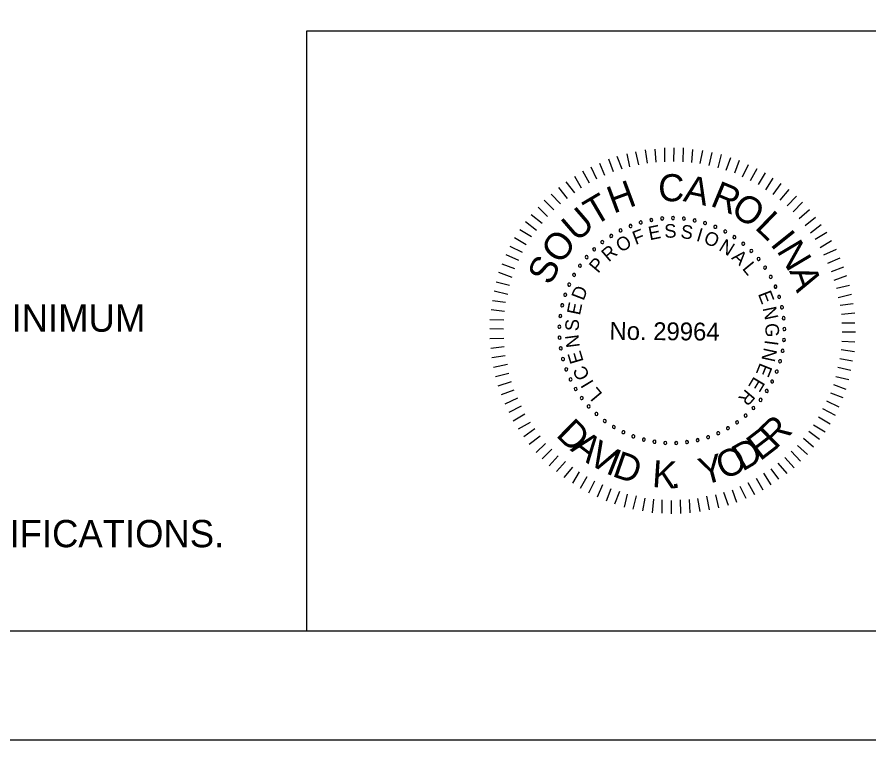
# Model space of a CAD drawing. Extents: x -225.1 to -152.9, y -16.8 to 27.2.
# Drawn here: x -182.47 to -174.66, y -16.78 to -10.15 of the extents above; entities that cross this region are included whole.
import ezdxf

# ---------------------------------------------------------------- set-up
doc = ezdxf.new("R2010")
doc.units = 0
for name, color, linetype in [('BR_BORDER LINES', 7, 'Continuous'), ('BR_TEXT', 7, 'Continuous'), ('Level 31', 7, 'Continuous')]:
    doc.layers.add(name, color=color, linetype=linetype)

msp = doc.modelspace()

# ---------------------------------------------------------------- linework, layer by layer
at = {"layer": 'BR_BORDER LINES'}
for p, q in [((-179.8094, -10.276), (-169.079, -10.276)), ((-179.8094, -15.7761), (-179.8094, -10.276)), ((-221.4105, -15.7762), (-154.0784, -15.7762))]:
    msp.add_line(p, q, dxfattribs=at)
at = {"layer": 'BR_TEXT'}
for p, q in [((-176.8476, -11.5246), (-176.8741, -11.4026)), ((-176.765, -11.5047), (-176.7933, -11.386)), ((-176.686, -11.4899), (-176.7039, -11.3679)), ((-176.607, -11.4819), (-176.6146, -11.3601)), ((-176.528, -11.4774), (-176.5269, -11.3487)), ((-176.4439, -11.4731), (-176.4429, -11.3494)), ((-176.3598, -11.4788), (-176.3553, -11.3502)), ((-176.2792, -11.4847), (-176.2696, -11.3629)), ((-176.202, -11.4939), (-176.1804, -11.3722)), ((-176.1215, -11.51), (-176.093, -11.3918)), ((-176.9991, -11.5697), (-177.0409, -11.4526)), ((-176.9199, -11.5446), (-176.9636, -11.4293)), ((-176.0393, -11.5313), (-176.0073, -11.4097)), ((-175.9657, -11.5525), (-175.9218, -11.4379)), ((-175.8869, -11.5789), (-175.843, -11.4625)), ((-177.1506, -11.6371), (-177.2029, -11.5251)), ((-177.0765, -11.6034), (-177.1237, -11.4914)), ((-175.8151, -11.6138), (-175.7593, -11.5027)), ((-175.7433, -11.6488), (-175.6806, -11.5377)), ((-177.2903, -11.72), (-177.3512, -11.6114)), ((-177.2196, -11.6726), (-177.2804, -11.564)), ((-175.6681, -11.6854), (-175.6037, -11.5778)), ((-175.6015, -11.734), (-175.5337, -11.6264)), ((-177.4198, -11.8133), (-177.4997, -11.7131)), ((-177.3525, -11.7625), (-177.4306, -11.6605)), ((-175.535, -11.7775), (-175.462, -11.6768)), ((-177.4855, -11.8626), (-177.5688, -11.7727)), ((-175.4702, -11.8294), (-175.3887, -11.7306)), ((-175.4071, -11.8798), (-175.3206, -11.7913)), ((-177.5443, -11.917), (-177.6328, -11.8288)), ((-175.3509, -11.9351), (-175.2644, -11.8484)), ((-177.6031, -11.9784), (-177.69, -11.8935)), ((-175.2948, -11.9975), (-175.1997, -11.9141)), ((-177.7055, -12.108), (-177.8043, -12.0282)), ((-177.6535, -12.0415), (-177.7524, -11.9634)), ((-175.2404, -12.0614), (-175.1471, -11.9849)), ((-177.7489, -12.1659), (-177.8565, -12.0998)), ((-175.1929, -12.1287), (-175.0944, -12.0506)), ((-177.7976, -12.2394), (-177.9051, -12.175)), ((-175.1488, -12.1874), (-175.0435, -12.1231)), ((-177.8325, -12.3077), (-177.9452, -12.2519)), ((-175.1047, -12.2616), (-174.9978, -12.199)), ((-177.8674, -12.3813), (-177.9819, -12.3305)), ((-175.0693, -12.3305), (-174.9538, -12.2766)), ((-177.9024, -12.4582), (-178.0187, -12.4143)), ((-175.0338, -12.4047), (-174.9201, -12.3558)), ((-177.927, -12.5386), (-178.0502, -12.493)), ((-175.0001, -12.4822), (-174.8865, -12.4402)), ((-174.9734, -12.563), (-174.858, -12.5194)), ((-177.9516, -12.6105), (-178.0733, -12.5804)), ((-174.9533, -12.6353), (-174.833, -12.6071)), ((-177.9661, -12.6945), (-178.0911, -12.6626)), ((-174.9369, -12.7196), (-174.8165, -12.6897)), ((-177.9872, -12.7665), (-178.109, -12.75)), ((-174.9203, -12.7918), (-174.8018, -12.7773)), ((-177.9965, -12.8487), (-178.1199, -12.834)), ((-174.9073, -12.8742), (-174.7853, -12.8616)), ((-178.0023, -12.9277), (-178.131, -12.9266)), ((-174.9045, -12.9532), (-174.7843, -12.9542)), ((-178.0065, -13.01), (-178.1317, -13.0089)), ((-174.9, -13.0356), (-174.7782, -13.0366)), ((-178.0037, -13.0958), (-178.1324, -13.0982)), ((-174.9059, -13.1214), (-174.7857, -13.1259)), ((-177.9992, -13.1731), (-178.1229, -13.1875)), ((-174.91, -13.1986), (-174.7882, -13.2151)), ((-177.9913, -13.2555), (-178.1133, -13.2735)), ((-177.9714, -13.3347), (-178.0969, -13.3611)), ((-174.9243, -13.2809), (-174.8061, -13.3008)), ((-177.9583, -13.4189), (-178.0804, -13.4471)), ((-174.9422, -13.3597), (-174.8222, -13.3881)), ((-177.9349, -13.4928), (-178.0588, -13.5348)), ((-174.96, -13.4437), (-174.8401, -13.4738)), ((-177.9115, -13.5703), (-178.0286, -13.6123)), ((-174.9812, -13.5172), (-174.8666, -13.5611)), ((-177.8778, -13.6444), (-177.9932, -13.6983)), ((-175.0443, -13.6678), (-174.9314, -13.7236)), ((-175.0093, -13.5943), (-174.8964, -13.6381)), ((-177.8441, -13.7168), (-177.9578, -13.7759)), ((-175.0809, -13.7396), (-174.9664, -13.8006)), ((-177.8104, -13.7909), (-177.919, -13.8535)), ((-175.1176, -13.8131), (-175.0117, -13.8775)), ((-177.7629, -13.8651), (-177.8716, -13.9277)), ((-175.1628, -13.8865), (-175.0586, -13.9509)), ((-177.7205, -13.9238), (-177.8206, -13.9967)), ((-175.2079, -13.9445), (-175.1107, -14.0191)), ((-177.6696, -13.9911), (-177.7698, -14.0693)), ((-177.6203, -14.0584), (-177.7086, -14.1401)), ((-175.2565, -14.011), (-175.1645, -14.0908)), ((-177.5624, -14.1105), (-177.6524, -14.2007)), ((-175.3691, -14.1286), (-175.2839, -14.2202)), ((-175.3119, -14.0775), (-175.2182, -14.1607)), ((-177.5046, -14.171), (-177.5894, -14.2629)), ((-175.4262, -14.1882), (-175.3412, -14.2815)), ((-177.4397, -14.223), (-177.5212, -14.3168)), ((-177.3732, -14.2751), (-177.453, -14.3705)), ((-175.5557, -14.2901), (-175.4844, -14.3868)), ((-175.4901, -14.2391), (-175.4102, -14.3342)), ((-177.3118, -14.3185), (-177.3744, -14.4226)), ((-177.2418, -14.3636), (-177.3044, -14.4713)), ((-175.623, -14.3324), (-175.5569, -14.4376)), ((-177.1735, -14.4037), (-177.2276, -14.5148)), ((-177.0999, -14.4386), (-177.1489, -14.5498)), ((-175.8385, -14.449), (-175.7846, -14.5611)), ((-175.7661, -14.4153), (-175.7053, -14.5274)), ((-175.6903, -14.3764), (-175.6277, -14.4851)), ((-177.0231, -14.4736), (-177.0668, -14.5865)), ((-176.9443, -14.4982), (-176.9899, -14.6146)), ((-176.8724, -14.5229), (-176.9008, -14.6411)), ((-175.9901, -14.5061), (-175.9481, -14.6232)), ((-175.9109, -14.4828), (-175.8689, -14.5964)), ((-176.7901, -14.5373), (-176.8204, -14.6607)), ((-176.7114, -14.5603), (-176.7312, -14.6768)), ((-176.6325, -14.5695), (-176.6421, -14.693)), ((-176.5535, -14.5753), (-176.5546, -14.6989)), ((-176.4695, -14.5811), (-176.4705, -14.703)), ((-176.3854, -14.5767), (-176.3829, -14.7003)), ((-176.3047, -14.5722), (-176.2971, -14.6959)), ((-176.2274, -14.5643), (-176.2077, -14.6811)), ((-176.1465, -14.5426), (-176.1201, -14.6664)), ((-176.0641, -14.5296), (-176.0341, -14.6482))]:
    msp.add_line(p, q, dxfattribs=at)
for centre, start, end in [((-176.7478, -12.0329), 16.14222, 196.14222), ((-176.7478, -12.0329), 196.14222, 16.14222), ((-176.6508, -12.0101), 10.60376, 190.60376), ((-176.6508, -12.0101), 190.60376, 10.60376), ((-176.552, -11.9967), 5.06529, 185.06529), ((-176.552, -11.9967), 185.06529, 5.06529), ((-176.4524, -11.9929), 359.52683, 179.52683), ((-176.4524, -11.9929), 179.52683, 359.52683), ((-176.353, -11.9987), 173.98837, 353.98837), ((-176.353, -11.9987), 353.98837, 173.98837), ((-176.2545, -12.0141), 168.44991, 348.44991), ((-176.2545, -12.0141), 348.44991, 168.44991), ((-176.158, -12.039), 342.91145, 162.91145), ((-176.9329, -12.1061), 27.21914, 207.21914), ((-176.9329, -12.1061), 207.21914, 27.21914), ((-176.8421, -12.065), 21.68068, 201.68068), ((-176.8421, -12.065), 201.68068, 21.68068), ((-176.158, -12.039), 162.91145, 342.91145), ((-176.0643, -12.073), 157.37299, 337.37299), ((-176.0643, -12.073), 337.37299, 157.37299), ((-175.9744, -12.1159), 331.83453, 151.83453), ((-177.0194, -12.1558), 32.7576, 212.7576), ((-177.0194, -12.1558), 212.7576, 32.7576), ((-175.9744, -12.1159), 151.83453, 331.83453), ((-175.889, -12.1673), 146.29606, 326.29606), ((-175.889, -12.1673), 326.29606, 146.29606), ((-177.1006, -12.2135), 38.29606, 218.29606), ((-177.1006, -12.2135), 218.29606, 38.29606), ((-175.809, -12.2267), 140.7576, 320.7576), ((-175.809, -12.2267), 320.7576, 140.7576), ((-177.2445, -12.3511), 49.37299, 229.37299), ((-177.2445, -12.3511), 229.37299, 49.37299), ((-177.1759, -12.2788), 43.83453, 223.83453), ((-177.1759, -12.2788), 223.83453, 43.83453), ((-175.735, -12.2936), 135.21914, 315.21914), ((-175.735, -12.2936), 315.21914, 135.21914), ((-177.3058, -12.4297), 54.91145, 234.91145), ((-177.3058, -12.4297), 234.91145, 54.91145), ((-175.6679, -12.3673), 129.68068, 309.68068), ((-175.6679, -12.3673), 309.68068, 129.68068), ((-175.6082, -12.4471), 124.14222, 304.14222), ((-175.6082, -12.4471), 304.14222, 124.14222), ((-177.3592, -12.5138), 60.44991, 240.44991), ((-177.3592, -12.5138), 240.44991, 60.44991), ((-175.5565, -12.5323), 118.60376, 298.60376), ((-175.5565, -12.5323), 298.60376, 118.60376), ((-177.4043, -12.6027), 65.98837, 245.98837), ((-177.4043, -12.6027), 245.98837, 65.98837), ((-175.5133, -12.622), 113.06529, 293.06529), ((-175.5133, -12.622), 293.06529, 113.06529), ((-177.4406, -12.6955), 71.52683, 251.52683), ((-177.4406, -12.6955), 251.52683, 71.52683), ((-175.4789, -12.7156), 107.52683, 287.52683), ((-175.4789, -12.7156), 287.52683, 107.52683), ((-177.4678, -12.7914), 77.06529, 257.06529), ((-177.4678, -12.7914), 257.06529, 77.06529), ((-175.4537, -12.812), 101.98837, 281.98837), ((-175.4537, -12.812), 281.98837, 101.98837), ((-177.4856, -12.8894), 82.60376, 262.60376), ((-177.4856, -12.8894), 262.60376, 82.60376), ((-175.4379, -12.9104), 96.44991, 276.44991), ((-175.4379, -12.9104), 276.44991, 96.44991), ((-177.4938, -12.9888), 88.14222, 268.14222), ((-177.4938, -12.9888), 268.14222, 88.14222), ((-175.4317, -13.0099), 90.91145, 270.91145), ((-175.4317, -13.0099), 270.91145, 90.91145), ((-177.4924, -13.0884), 93.68068, 273.68068), ((-177.4924, -13.0884), 273.68068, 93.68068), ((-175.4351, -13.1095), 85.37299, 265.37299), ((-175.4351, -13.1095), 265.37299, 85.37299), ((-177.4814, -13.1875), 99.21914, 279.21914), ((-177.4814, -13.1875), 279.21914, 99.21914), ((-175.4482, -13.2083), 79.83453, 259.83453), ((-175.4482, -13.2083), 259.83453, 79.83453), ((-177.4609, -13.285), 104.7576, 284.7576), ((-177.4609, -13.285), 284.7576, 104.7576), ((-175.4707, -13.3054), 74.29606, 254.29606), ((-175.4707, -13.3054), 254.29606, 74.29606), ((-177.4311, -13.3801), 110.29606, 290.29606), ((-177.4311, -13.3801), 290.29606, 110.29606), ((-175.5024, -13.3998), 68.7576, 248.7576), ((-175.5024, -13.3998), 248.7576, 68.7576), ((-177.3922, -13.4719), 115.83453, 295.83453), ((-177.3922, -13.4719), 295.83453, 115.83453), ((-175.5432, -13.4908), 63.21914, 243.21914), ((-175.5432, -13.4908), 243.21914, 63.21914), ((-177.3447, -13.5594), 121.37299, 301.37299), ((-177.3447, -13.5594), 301.37299, 121.37299), ((-175.5925, -13.5774), 57.68068, 237.68068), ((-175.5925, -13.5774), 237.68068, 57.68068), ((-177.2889, -13.642), 126.91145, 306.91145), ((-177.2889, -13.642), 306.91145, 126.91145), ((-175.6499, -13.6588), 52.14222, 232.14222), ((-175.6499, -13.6588), 232.14222, 52.14222), ((-177.2254, -13.7189), 132.44991, 312.44991), ((-177.2254, -13.7189), 312.44991, 132.44991), ((-175.715, -13.7343), 46.60376, 226.60376), ((-175.715, -13.7343), 226.60376, 46.60376), ((-177.1548, -13.7892), 137.98837, 317.98837), ((-177.1548, -13.7892), 317.98837, 137.98837), ((-175.787, -13.8032), 41.06529, 221.06529), ((-175.787, -13.8032), 221.06529, 41.06529), ((-177.0778, -13.8524), 143.52683, 323.52683), ((-177.0778, -13.8524), 323.52683, 143.52683), ((-176.995, -13.9079), 149.06529, 329.06529), ((-176.995, -13.9079), 329.06529, 149.06529), ((-175.8653, -13.8648), 35.52683, 215.52683), ((-175.8653, -13.8648), 215.52683, 35.52683), ((-176.9072, -13.9551), 154.60376, 334.60376), ((-176.9072, -13.9551), 334.60376, 154.60376), ((-176.8153, -13.9936), 340.14222, 160.14222), ((-176.038, -13.964), 24.44991, 204.44991), ((-176.038, -13.964), 204.44991, 24.44991), ((-175.9493, -13.9186), 29.98837, 209.98837), ((-175.9493, -13.9186), 209.98837, 29.98837), ((-176.8153, -13.9936), 160.14222, 340.14222), ((-176.7201, -14.0231), 165.68068, 345.68068), ((-176.7201, -14.0231), 345.68068, 165.68068), ((-176.6225, -14.0432), 171.21914, 351.21914), ((-176.6225, -14.0432), 351.21914, 171.21914), ((-176.5234, -14.0539), 356.7576, 176.7576), ((-176.5234, -14.0539), 176.7576, 356.7576), ((-176.4237, -14.0549), 2.29606, 182.29606), ((-176.4237, -14.0549), 182.29606, 2.29606), ((-176.3244, -14.0463), 7.83453, 187.83453), ((-176.3244, -14.0463), 187.83453, 7.83453), ((-176.2264, -14.0282), 13.37299, 193.37299), ((-176.2264, -14.0282), 193.37299, 13.37299), ((-176.1307, -14.0006), 18.91145, 198.91145), ((-176.1307, -14.0006), 198.91145, 18.91145)]:
    msp.add_arc(centre, 0.014, start, end, dxfattribs=at)
at = {"layer": 'Level 31'}
msp.add_lwpolyline([(-225.0771, -16.7761), (-153.0772, -16.7761), (-153.0772, 27.2239), (-225.0771, 27.2239)], close=True, dxfattribs=at)

# ---------------------------------------------------------------- texts
at = {"layer": 'BR_TEXT'}
for s, height, rotation, p in [('C', 0.2482, 359.54822, (-176.5894, -11.8377)), ('A', 0.2482, 348.19813, (-176.3665, -11.8361)), ('H', 0.2482, 20.36371, (-176.9983, -11.9543)), ('R', 0.2482, 337.43439, (-176.1201, -11.8759)), ('T', 0.2482, 30.49921, (-177.174, -12.0694)), ('O', 0.2478, 326.58689, (-175.9356, -11.9494)), ('U', 0.2482, 40.80225, (-177.3364, -12.2189)), ('L', 0.2482, 315.94879, (-175.7105, -12.0849)), ('F', 0.1245, 20.61271, (-176.7957, -12.2401)), ('E', 0.1245, 11.41035, (-176.6653, -12.1967)), ('S', 0.1245, 2.20798, (-176.5297, -12.1748)), ('S', 0.1245, 352.66081, (-176.3872, -12.1752)), ('I', 0.1245, 343.11363, (-176.2467, -12.1992)), ('I', 0.2482, 308.66128, (-175.5677, -12.2335)), ('O', 0.2482, 52.0267, (-177.4855, -12.4268)), ('O', 0.1245, 30.84774, (-176.9304, -12.3121)), ('O', 0.1245, 338.43918, (-176.1799, -12.2195)), ('N', 0.1245, 328.20415, (-176.0406, -12.2823)), ('R', 0.1245, 40.39491, (-177.0427, -12.3999)), ('N', 0.2481, 300.70365, (-175.5065, -12.2923)), ('A', 0.1245, 318.65698, (-175.9227, -12.3623)), ('S', 0.2478, 63.25114, (-177.5762, -12.618)), ('P', 0.1245, 49.94209, (-177.1389, -12.5051)), ('L', 0.1245, 309.45461, (-175.8231, -12.457)), ('A', 0.2482, 289.47921, (-175.3881, -12.4784)), ('D', 0.1245, 69.03644, (-177.2728, -12.7557)), ('E', 0.1245, 291.049, (-175.6753, -12.6876)), ('E', 0.1245, 78.23881, (-177.3059, -12.889)), ('N', 0.1245, 281.84664, (-175.631, -12.8177)), ('S', 0.1245, 87.78598, (-177.3173, -13.0311)), ('No. 29964', 0.16349, 359.52683, (-177.0351, -13.1079)), ('G', 0.1245, 272.29946, (-175.6075, -12.9583)), ('N', 0.1245, 97.33316, (-177.305, -13.1731)), ('I', 0.1245, 262.40836, (-175.6082, -13.1059)), ('N', 0.1245, 257.73391, (-175.6173, -13.1752)), ('E', 0.1245, 106.53552, (-177.271, -13.3062)), ('C', 0.1245, 116.42662, (-177.2113, -13.4412)), ('E', 0.1245, 248.18673, (-175.6533, -13.313)), ('I', 0.1245, 121.10107, (-177.1751, -13.501)), ('E', 0.1245, 238.98437, (-175.7093, -13.4385)), ('L', 0.1245, 129.95951, (-177.0938, -13.6053)), ('R', 0.1245, 229.78201, (-175.7845, -13.5535)), ('R', 0.2471, 44.59474, (-175.5131, -14.1176)), ('D', 0.2471, 315.40526, (-177.5348, -13.9865)), ('A', 0.2471, 322.83772, (-177.4016, -14.1178)), ('E', 0.2471, 37.53391, (-175.6543, -14.2254)), ('V', 0.2471, 330.51792, (-177.2473, -14.2342)), ('D', 0.2471, 30.10145, (-175.8161, -14.3193)), ('I', 0.2471, 338.19813, (-177.0789, -14.3289)), ('D', 0.2471, 340.79949, (-177.0191, -14.3558)), ('O', 0.2471, 22.42125, (-175.9946, -14.3934)), ('K', 0.2471, 356.09796, (-176.6486, -14.4569)), ('Y', 0.2471, 14.86491, (-176.1783, -14.4424)), ('.', 0.2471, 3.15879, (-176.4713, -14.4696))]:
    msp.add_text(s, height=height, rotation=rotation, dxfattribs=at).set_placement(p)
for s, p in [('THE LOCATION OF WELDED SPLICES ON ADJACENT HOOPS SHALL BE STAGGERED AROUND PERIMETER OF COLUMN AND SHAFT BY A MINIMUM', (-205.1048, -13.0348)), ('CROSSHOLE SONIC LOGGING IS TO BE CONDUCTED IN ACCORDANCE WITH SECTION 727 OF THE 2007 EDITION OF THE STANDARD SPECIFICATIONS.', (-205.1048, -15.0098))]:
    msp.add_text(s, height=0.2499994, dxfattribs=at).set_placement(p)

doc.saveas('drawing.dxf')
